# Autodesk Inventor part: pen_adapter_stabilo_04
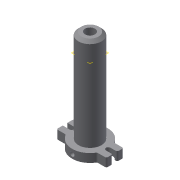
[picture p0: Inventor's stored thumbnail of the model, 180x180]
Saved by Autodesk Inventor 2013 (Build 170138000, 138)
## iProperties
Created: 2013-11
Part Number: pen_adapter_stabilo_04
Material: Generic
Document SubType Name: Modeling
Designer: Jonas
Density: 1 g/cm^3
Author: Jonas
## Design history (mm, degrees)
sketch "Sketch2"
  geometry: C1 r 12.5 at (0, 0); 1 further point
  constraints: 1 centre point, 1 coincident
  dimensions: "d3" = 25 diameter of C1
extrude "Extrusion2" new body sketch "Sketch2" distance "d4" = 6; taper "d5" = 0 deg
sketch "Sketch6"
  geometry: L1 (-17.5, 6)-(17.5, 6); L2 (17.5, 6)-(17.5, -6); L3 (17.5, -6)-(-17.5, -6); L4 (-17.5, -6)-(-17.5, 6); L5 (-17.5, 6)-(17.5, -6); L6 (17.5, 6)-(-17.5, -6); 1 further point
  constraints: 12 end point, 2 midpoint, 2 parallel, 1 horizontal, 1 perpendicular
  dimensions: "d20" = 35 distance of L2.end L3.end; "d21" = 12 distance of L1.end L2.end
extrude "Extrusion6" join sketch "Sketch6" stored distance "d22" = 27.72; taper "d23" = 0 deg
sketch "Sketch10"
  geometry: C1 r 3.25 at (-12.75, 0); A1 r 12.5 centre (0, 0) between (-10.966, -6) and (10.966, -6) reference
  constraints: 1 centre point, 1 horizontal alignment
  dimensions: "d34" = 6.5 diameter of C1; "d35" = 12.75 distance of A1.centre C1.centre (computed from d34)
extrude "Extrusion9" cut sketch "Sketch10" distance "d36" = 2; taper "d37" = 0 deg
sketch "Sketch11"
  geometry: L1 (-17.5, 6)-(-17.5, -6) reference; L2 (-12.75, 1.6)-(-17.5, 1.6); L3 (-12.75, -1.6)-(-17.5, -1.6); L4 (-17.5, 1.6)-(-17.5, -1.6); C1 r 3.25 at (-12.75, 0) reference; A1 r 1.6 centre (-12.75, 0) between (-12.75, -1.6) and (-12.75, 1.6)
  constraints: 6 end point, 2 perpendicular, 2 point on circle, 2 point on line, 2 tangent, 1 centre point, 1 coincident, 1 parallel
  dimensions: "d53" = 3.2 distance between parallel lines of L3 L2
extrude "Extrusion10" cut sketch "Sketch11" stored distance "d55" = 1; taper "d56" = 0 deg
chamfer "Chamfer4" distance "d57" = 1; stored, may be unused: second distance "d58" = 2, angle "d59" = 45 deg
fillet "Fillet2" dims "d41" = 1
mirror "Mirror1"
sketch "Sketch3"
  geometry: C1 r 12.5 at (0, 0) reference; C2 r 8.05 at (0, 0)
  constraints: 1 centre point, 1 coincident
  dimensions: "d7" = 16.1 diameter of C2
extrude "Extrusion3" join sketch "Sketch3" distance "d8" = 65; taper "d9" = 0 deg
sketch "Sketch5"
  geometry: C1 r 12.5 at (0, 0) reference; C2 r 3.5 at (0, 0)
  constraints: 1 centre point, 1 coincident
  dimensions: "d13" = 7 diameter of C2
extrude "Extrusion5" cut sketch "Sketch5" stored distance "d14" = 27.72; taper "d15" = 0 deg
chamfer "Chamfer1" distance "d16" = 2; stored, may be unused: second distance "d17" = 2, angle "d18" = 45 deg
fillet "Fillet3" dims "d42" = 1
sketch "Sketch13"
  geometry: C1 r 1.5 at (0, 2.85); 1 further point
  constraints: 1 centre point, 1 vertical alignment
  dimensions: "d60" = 3 diameter of C1; "d61" = 2.85 distance of point (0, 0) C1.centre (computed from d60)
extrude "Extrusion11" cut sketch "Sketch13" stored distance "d62" = 1; taper "d63" = 0 deg
workplane "Work Plane1"
sketch "Sketch14"
  geometry: L1 (4.1, -2.367)-(0, -4.734); L2 (0, -4.734)-(-4.1, -2.367); L3 (-4.1, -2.367)-(-4.1, 2.367); L4 (-4.1, 2.367)-(0, 4.734); L5 (0, 4.734)-(4.1, 2.367); L6 (4.1, 2.367)-(4.1, -2.367); 2 further points
  constraints: 12 end point, 1 coincident, 1 vertical alignment, 13 other
  dimensions: "d66" = 8.2 distance between parallel lines of L6 L3
extrude "Extrusion12" cut sketch "Sketch14" stored distance "d67" = 1; taper "d68" = 0 deg
chamfer "Chamfer5" distance "d69" = 1; stored, may be unused: second distance "d70" = 2, angle "d71" = 45 deg
body "Solid1"
other parameters: "d65" = -13
